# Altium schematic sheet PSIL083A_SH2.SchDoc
size 558 x 431 mm; Date: Not shown in title block; ApprovedBy: Not shown in title block; CheckedBy: Not shown in title block; Author: Not shown in title block; CompanyName: Not shown in title block; Engineer: Not shown in title block; Organization: Not shown in title block; Address1: Not shown in title block; Address2: Not shown in title block; Address3: Not shown in title block; Address4: Not shown in title block; DocumentNumber: 2; Revision: Use project parameter SCH_Rev; SheetNumber: 2; SheetTotal: 3; PageSetup: Record=PageOptions¦CenterHorizontal=True¦CenterVertical=True¦PrintScale=1.00¦XCorrection=1.00¦YCorrection=1.00¦PrintKind=0¦BorderSize=5000000¦LeftOffset=0¦BottomOffset=0¦Orientation=2¦PaperLength=1000¦PaperWidth=1000¦Scale=100¦PaperSource=15¦PrintQuality=600¦MediaType=1¦DitherType=10¦PaperKind=Letter¦PrintScaleMode=1
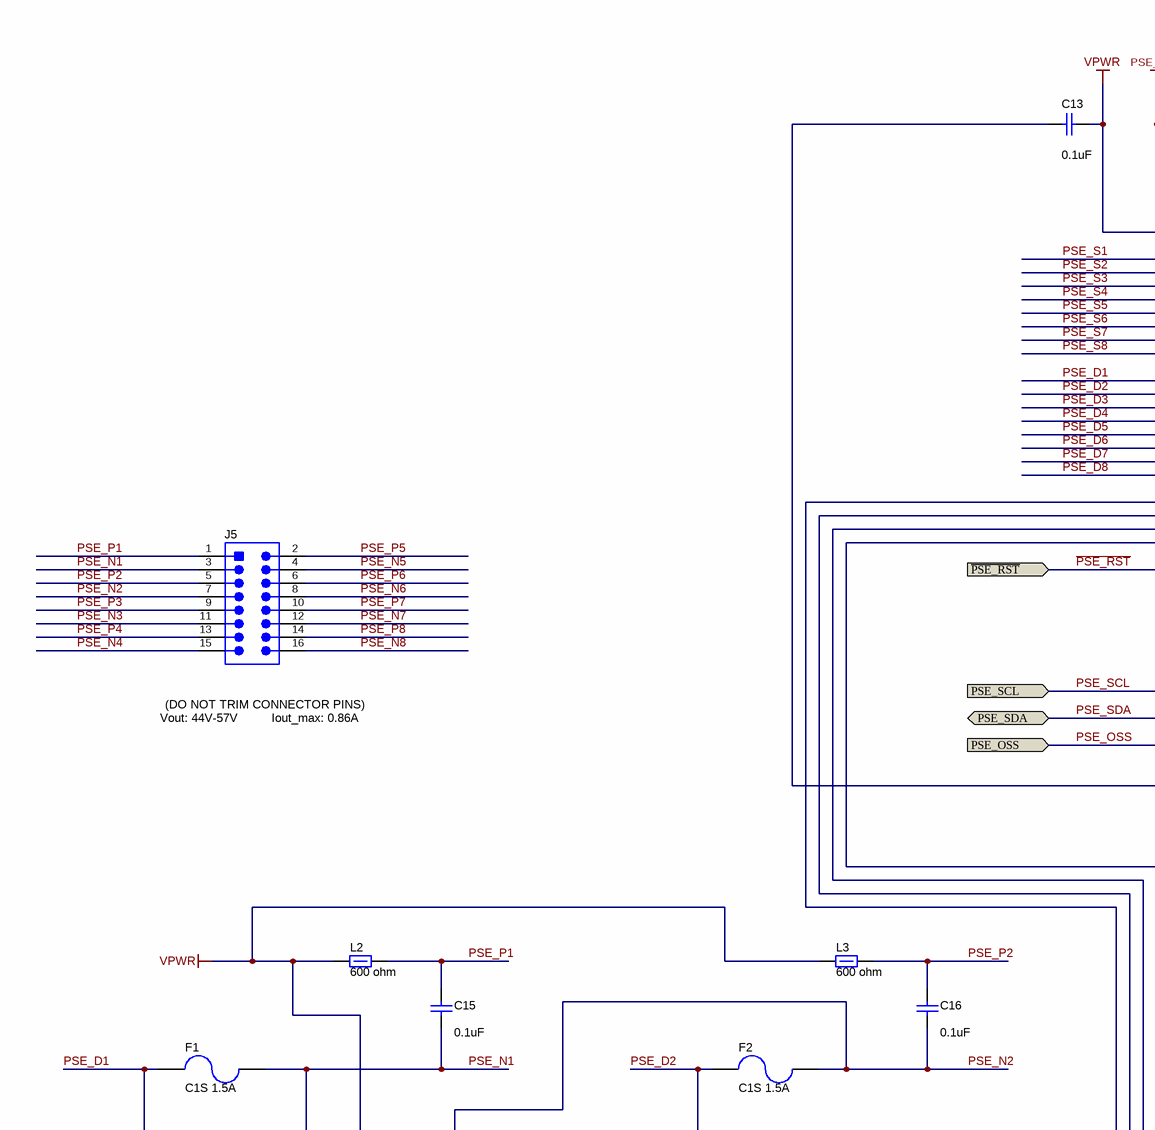
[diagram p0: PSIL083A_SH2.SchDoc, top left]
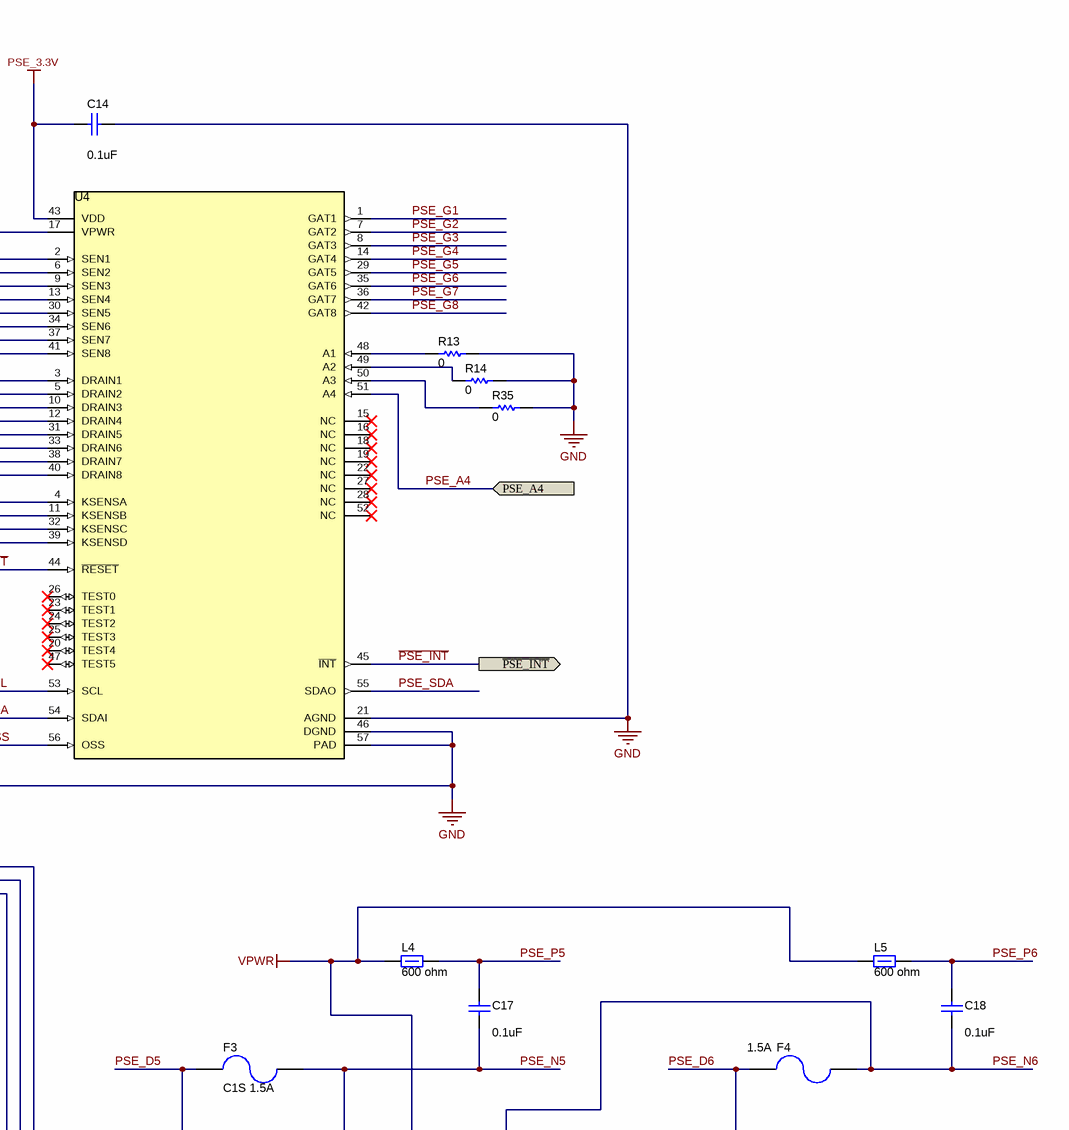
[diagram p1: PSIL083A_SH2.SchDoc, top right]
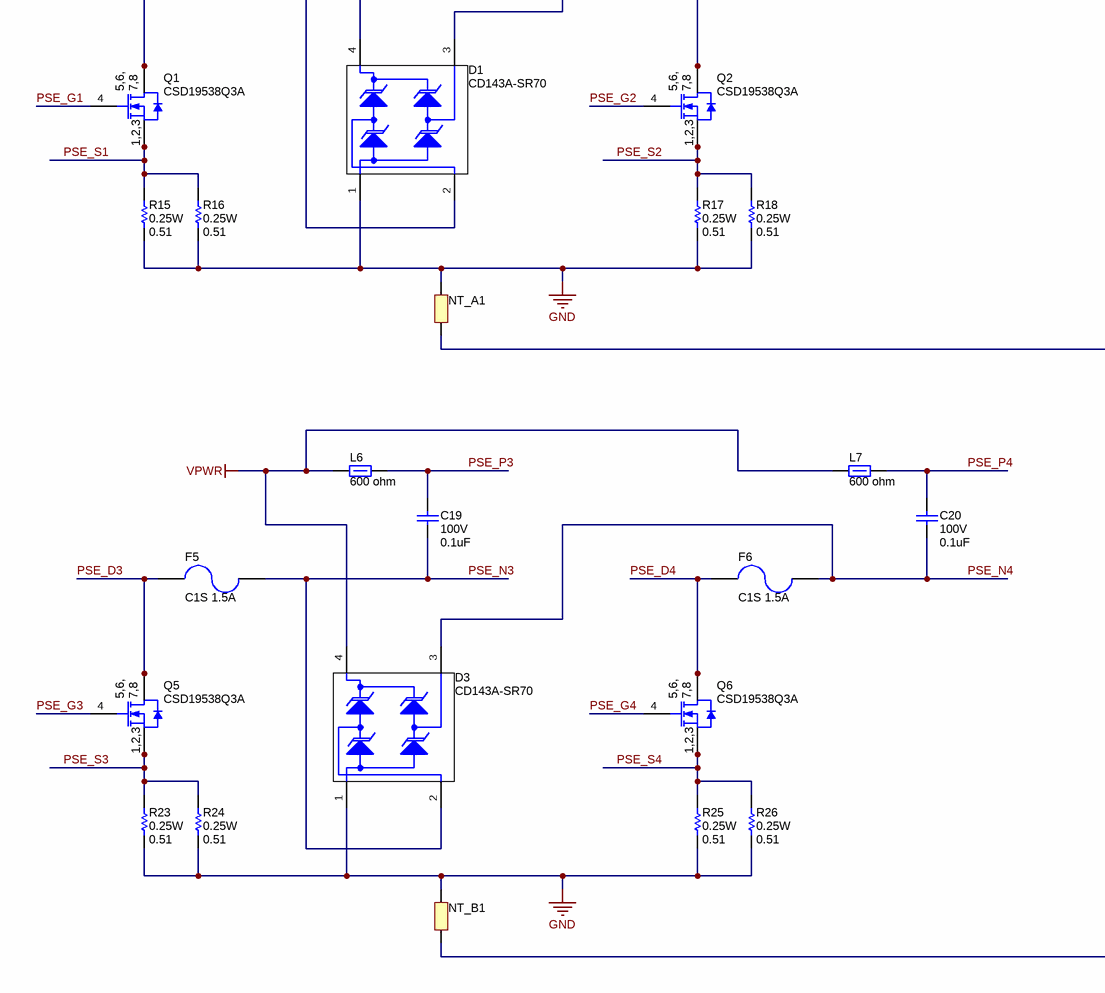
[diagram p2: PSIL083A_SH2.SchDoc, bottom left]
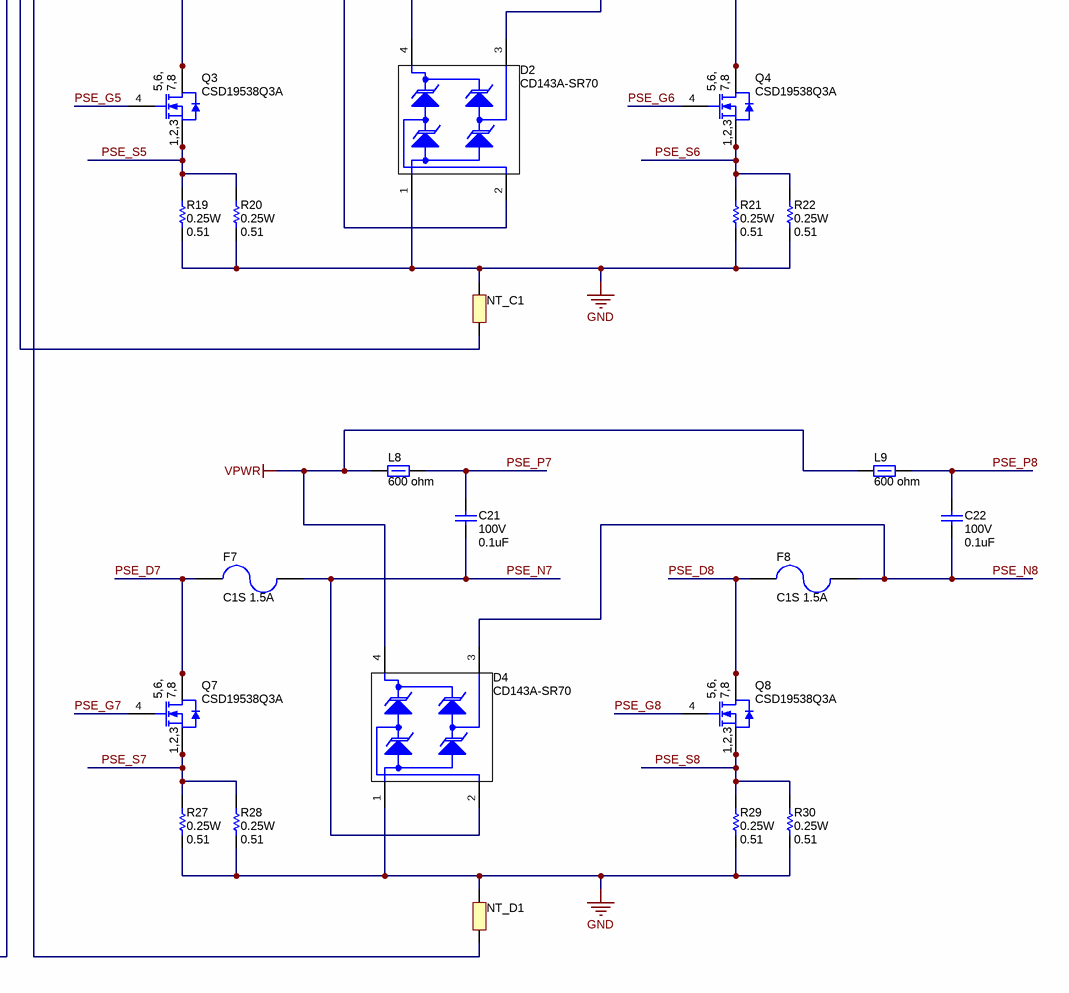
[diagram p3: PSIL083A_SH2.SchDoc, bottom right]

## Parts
C13  ValueDisplayed: 0.1uF  [0603]  (hidden comment: CGA3E3X7S2A104K080AB)
C14  ValueDisplayed: 0.1uF  [0805_HV]  (hidden comment: C0805C104K4RACTU)
C15  ValueDisplayed: 0.1uF  [0805_HV]  (hidden comment: C2012X7R2A104K125AA)
C16  ValueDisplayed: 0.1uF  [0805_HV]  (hidden comment: C2012X7R2A104K125AA)
C17  ValueDisplayed: 0.1uF  [0805_HV]  (hidden comment: C2012X7R2A104K125AA)
C18  ValueDisplayed: 0.1uF  [0805_HV]  (hidden comment: C2012X7R2A104K125AA)
C19  VDC_V: 100V  ValueDisplayed: 0.1uF  [0805_HV]  (hidden comment: C2012X7R2A104K125AA)
C20  VDC_V: 100V  ValueDisplayed: 0.1uF  [0805_HV]  (hidden comment: C2012X7R2A104K125AA)
C21  VDC_V: 100V  ValueDisplayed: 0.1uF  [0805_HV]  (hidden comment: C2012X7R2A104K125AA)
C22  VDC_V: 100V  ValueDisplayed: 0.1uF  [0805_HV]  (hidden comment: C2012X7R2A104K125AA)
D1  CD143A-SR70  [SOT-143-4]
D2  CD143A-SR70  [SOT-143-4]
D3  CD143A-SR70  [SOT-143-4]
D4  CD143A-SR70  [SOT-143-4]
F1  C1S 1.5A  [1206]
F2  C1S 1.5A  [1206]
F3  C1S 1.5A  [1206]
F4  Irating_A: 1.5A  [1206]  (hidden comment: C1S 1.5)
F5  C1S 1.5A  [1206]
F6  C1S 1.5A  [1206]
F7  C1S 1.5A  [1206]
F8  C1S 1.5A  [1206]
J5  TSW-108-09-G-D  [TSW-108-07-G-D]  (value not drawn)
L2  ValueDisplayed: 600 ohm  [0603]  (hidden comment: MPZ1608S601ATD25)
L3  ValueDisplayed: 600 ohm  [0603]  (hidden comment: MPZ1608S601ATD25)
L4  ValueDisplayed: 600 ohm  [0603]  (hidden comment: MPZ1608S601ATD25)
L5  ValueDisplayed: 600 ohm  [0603]  (hidden comment: MPZ1608S601ATD25)
L6  ValueDisplayed: 600 ohm  [0603]  (hidden comment: MPZ1608S601ATD25)
L7  ValueDisplayed: 600 ohm  [0603]  (hidden comment: MPZ1608S601ATD25)
L8  ValueDisplayed: 600 ohm  [0603]  (hidden comment: MPZ1608S601ATD25)
L9  ValueDisplayed: 600 ohm  [0603]  (hidden comment: MPZ1608S601ATD25)
NT_A1  Net-Tie  [Net-Tie_10milWide_30milLong]  (value not drawn)  (net tie, no BOM)
NT_B1  Net-Tie  [Net-Tie_10milWide_30milLong]  (value not drawn)  (net tie, no BOM)
NT_C1  Net-Tie  [Net-Tie_10milWide_30milLong]  (value not drawn)  (net tie, no BOM)
NT_D1  Net-Tie  [Net-Tie_10milWide_30milLong]  (value not drawn)  (net tie, no BOM)
Q1  CSD19538Q3A  [DNH0008A_NV]
Q2  CSD19538Q3A  [DNH0008A_NV]
Q3  CSD19538Q3A  [DNH0008A_NV]
Q4  CSD19538Q3A  [DNH0008A_NV]
Q5  CSD19538Q3A  [DNH0008A_NV]
Q6  CSD19538Q3A  [DNH0008A_NV]
Q7  CSD19538Q3A  [DNH0008A_NV]
Q8  CSD19538Q3A  [DNH0008A_NV]
R13  ValueDisplayed: 0  [0402]  (hidden comment: ERJ-2GE0R00X)
R14  ValueDisplayed: 0  [0402]  (hidden comment: ERJ-2GE0R00X)
R15  Value2: 0.25W  ValueDisplayed: 0.51  [0805L]  (hidden comment: CRM0805-FX-R510ELF)
R16  Value2: 0.25W  ValueDisplayed: 0.51  [0805L]  (hidden comment: CRM0805-FX-R510ELF)
R17  Value2: 0.25W  ValueDisplayed: 0.51  [0805L]  (hidden comment: CRM0805-FX-R510ELF)
R18  Value2: 0.25W  ValueDisplayed: 0.51  [0805L]  (hidden comment: CRM0805-FX-R510ELF)
R19  Value2: 0.25W  ValueDisplayed: 0.51  [0805L]  (hidden comment: CRM0805-FX-R510ELF)
R20  Value2: 0.25W  ValueDisplayed: 0.51  [0805L]  (hidden comment: CRM0805-FX-R510ELF)
R21  Value2: 0.25W  ValueDisplayed: 0.51  [0805L]  (hidden comment: CRM0805-FX-R510ELF)
R22  Value2: 0.25W  ValueDisplayed: 0.51  [0805L]  (hidden comment: CRM0805-FX-R510ELF)
R23  Value2: 0.25W  ValueDisplayed: 0.51  [0805L]  (hidden comment: CRM0805-FX-R510ELF)
R24  Value2: 0.25W  ValueDisplayed: 0.51  [0805L]  (hidden comment: CRM0805-FX-R510ELF)
R25  Value2: 0.25W  ValueDisplayed: 0.51  [0805L]  (hidden comment: CRM0805-FX-R510ELF)
R26  Value2: 0.25W  ValueDisplayed: 0.51  [0805L]  (hidden comment: CRM0805-FX-R510ELF)
R27  Value2: 0.25W  ValueDisplayed: 0.51  [0805L]  (hidden comment: CRM0805-FX-R510ELF)
R28  Value2: 0.25W  ValueDisplayed: 0.51  [0805L]  (hidden comment: CRM0805-FX-R510ELF)
R29  Value2: 0.25W  ValueDisplayed: 0.51  [0805L]  (hidden comment: CRM0805-FX-R510ELF)
R30  Value2: 0.25W  ValueDisplayed: 0.51  [0805L]  (hidden comment: CRM0805-FX-R510ELF)
R35  ValueDisplayed: 0  [0402]  (hidden comment: ERJ-2GE0R00X)
U4  TPS23880RTQR  [RTQ0056E]

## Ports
PSE_A4 (in), PSE_OSS (in), PSE_SCL (in), PSE_SDA (bidir), ~{PSE_INT} (out), ~{PSE_RST} (in)

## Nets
GND: C13.2 C14.2 D1.1(A) D2.1(A) D3.1(A) D4.1(A) NT_A1.2 NT_B1.2 NT_C1.2 NT_D1.2 R13.2 R14.2 R15.2 R16.2 R17.2 R18.2 R19.2 R20.2 R21.2 R22.2 R23.2 R24.2 R25.2 R26.2 R27.2 R28.2 R29.2 R30.2 R35.2 U4.21(AGND) U4.46(DGND) U4.57(PAD)
PSE_3.3V: C14.1 U4.43(VDD)
VPWR: C13.1 D1.4(K3) D2.4(K3) D3.4(K3) D4.4(K3) L2.1 L3.1 L4.1 L5.1 L6.1 L7.1 L8.1 L9.1 U4.17(VPWR)
~{PSE_INT}: U4.45(~{INT}) ; port ~{PSE_INT}
~{PSE_RST}: U4.44(~{RESET}) ; port ~{PSE_RST}
PSE_A4: U4.51(A4) ; port PSE_A4
PSE_D1: F1.2 Q1.5(D) Q1.6(D) Q1.7(D) Q1.8(D) Q1.9(D) U4.3(DRAIN1)
PSE_D2: F2.2 Q2.5(D) Q2.6(D) Q2.7(D) Q2.8(D) Q2.9(D) U4.5(DRAIN2)
PSE_D3: F5.2 Q5.5(D) Q5.6(D) Q5.7(D) Q5.8(D) Q5.9(D) U4.10(DRAIN3)
PSE_D4: F6.2 Q6.5(D) Q6.6(D) Q6.7(D) Q6.8(D) Q6.9(D) U4.12(DRAIN4)
PSE_D5: F3.2 Q3.5(D) Q3.6(D) Q3.7(D) Q3.8(D) Q3.9(D) U4.31(DRAIN5)
PSE_D6: F4.2 Q4.5(D) Q4.6(D) Q4.7(D) Q4.8(D) Q4.9(D) U4.33(DRAIN6)
PSE_D7: F7.2 Q7.5(D) Q7.6(D) Q7.7(D) Q7.8(D) Q7.9(D) U4.38(DRAIN7)
PSE_D8: F8.2 Q8.5(D) Q8.6(D) Q8.7(D) Q8.8(D) Q8.9(D) U4.40(DRAIN8)
PSE_G1: Q1.4(G) U4.1(GAT1)
PSE_G2: Q2.4(G) U4.7(GAT2)
PSE_G3: Q5.4(G) U4.8(GAT3)
PSE_G4: Q6.4(G) U4.14(GAT4)
PSE_G5: Q3.4(G) U4.29(GAT5)
PSE_G6: Q4.4(G) U4.35(GAT6)
PSE_G7: Q7.4(G) U4.36(GAT7)
PSE_G8: Q8.4(G) U4.42(GAT8)
PSE_N1: C15.2 D1.2(K1) F1.1 J5.3
PSE_N2: C16.2 D1.3(K2) F2.1 J5.7
PSE_N3: C19.2 D3.2(K1) F5.1 J5.11
PSE_N4: C20.2 D3.3(K2) F6.1 J5.15
PSE_N5: C17.2 D2.2(K1) F3.1 J5.4
PSE_N6: C18.2 D2.3(K2) F4.1 J5.8
PSE_N7: C21.2 D4.2(K1) F7.1 J5.12
PSE_N8: C22.2 D4.3(K2) F8.1 J5.16
PSE_OSS: U4.56(OSS) ; port PSE_OSS
PSE_P1: C15.1 J5.1 L2.2
PSE_P2: C16.1 J5.5 L3.2
PSE_P3: C19.1 J5.9 L6.2
PSE_P4: C20.1 J5.13 L7.2
PSE_P5: C17.1 J5.2 L4.2
PSE_P6: C18.1 J5.6 L5.2
PSE_P7: C21.1 J5.10 L8.2
PSE_P8: C22.1 J5.14 L9.2
PSE_S1: Q1.1(S) Q1.2(S) Q1.3(S) R15.1 R16.1 U4.2(SEN1)
PSE_S2: Q2.1(S) Q2.2(S) Q2.3(S) R17.1 R18.1 U4.6(SEN2)
PSE_S3: Q5.1(S) Q5.2(S) Q5.3(S) R23.1 R24.1 U4.9(SEN3)
PSE_S4: Q6.1(S) Q6.2(S) Q6.3(S) R25.1 R26.1 U4.13(SEN4)
PSE_S5: Q3.1(S) Q3.2(S) Q3.3(S) R19.1 R20.1 U4.30(SEN5)
PSE_S6: Q4.1(S) Q4.2(S) Q4.3(S) R21.1 R22.1 U4.34(SEN6)
PSE_S7: Q7.1(S) Q7.2(S) Q7.3(S) R27.1 R28.1 U4.37(SEN7)
PSE_S8: Q8.1(S) Q8.2(S) Q8.3(S) R29.1 R30.1 U4.41(SEN8)
PSE_SCL: U4.53(SCL) ; port PSE_SCL
PSE_SDA: U4.54(SDAI) U4.55(SDAO) ; port PSE_SDA
NetNT_A1_1: NT_A1.1 U4.4(KSENSA)
NetNT_B1_1: NT_B1.1 U4.11(KSENSB)
NetNT_C1_1: NT_C1.1 U4.32(KSENSC)
NetNT_D1_1: NT_D1.1 U4.39(KSENSD)
NetR13_1: R13.1 U4.48(A1)
NetR14_1: R14.1 U4.49(A2)
NetR35_1: R35.1 U4.50(A3)

Not connected (* = marked no-connect by the designer): U4 15(NC)* 16(NC)* 18(NC)* 19(NC)* 20(TEST4)* 22(NC)* 23(TEST1)* 24(TEST2)* 25(TEST3)* 26(TEST0)* 27(NC)* 28(NC)* 47(TEST5)* 52(NC)*

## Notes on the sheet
- Vout: 44V-57V
- (near J5) (DO NOT TRIM CONNECTOR PINS)
- Iout_max: 0.86A

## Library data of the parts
C13 = CMP-0007099-4: CAP, CERM, 0.1 uF, 100 V, +/- 10%, X7S, AEC-Q200 Grade 1, 0603; Manufacturer: TDK; TaMin_C: -55°C; ESR_ohm: 0.04959; Polarized: N; SizeAreaWB_mm2: 4.68; Value1: 0.04959 ohm; U/M: EA; Value: 0.1uF; TaMax_C: 125°C; SizeZ_mm: 1; SizeX_mm: 1.6; SizeY_mm: 0.8; Value2: 100V; SizeArea_mm2: 1.28; CompType: Capacitor; AEC Qualified: Y; Cap_F: 100nF; IRMS_A: 7.51618dA; AEC Category: Q200
C14 = CMP-0007724-2: CAP, CERM, 0.1 uF, 16 V, +/- 10%, X7R, 0805; Manufacturer: Kemet; TaMin_C: -55°C; ESR_ohm: 0.064; Polarized: N; SizeAreaWB_mm2: 6.75; Value1: 0.064 ohm; U/M: EA; Value: 0.1uF; TaMax_C: 125°C; SizeZ_mm: 1.45; SizeX_mm: 2; SizeY_mm: 1.25; Cap_Case: 0805; SizeArea_mm2: 2.5; CompType: Capacitor; Cap_F: 100nF; VDC_V: 16V; IRMS_A: 1.64A; AEC Category: Q200
C15-C18 = CMP-0007886-2: CAP, CERM, 0.1 uF, 100 V, +/- 10%, X7R, 0805; Manufacturer: TDK; TaMin_C: -55°C; ESR_ohm: 0.020726; Polarized: N; SizeAreaWB_mm2: 6.75; Value1: 0.020726 ohm; U/M: EA; Value: 0.1uF; TaMax_C: 125°C; SizeZ_mm: 1.45; SizeX_mm: 2; SizeY_mm: 1.25; Cap_Case: 0805; Value2: 100V; SizeArea_mm2: 2.5; CompType: Capacitor; Cap_F: 100nF; IRMS_A: 1.456A; AEC Category: Q200
C19-C22 = CMP-0007886-2: CAP, CERM, 0.1 uF, 100 V, +/- 10%, X7R, 0805; Manufacturer: TDK; TaMin_C: -55°C; ESR_ohm: 0.020726; Polarized: N; SizeAreaWB_mm2: 6.75; Value1: 0.020726 ohm; U/M: EA; Value: 0.1uF; TaMax_C: 125°C; SizeZ_mm: 1.45; SizeX_mm: 2; SizeY_mm: 1.25; Cap_Case: 0805; SizeArea_mm2: 2.5; Cap_F: 100nF; IRMS_A: 1.456A; AEC Category: Q200
D1-D4 = CMP-0002018-2: ESD Suppressor Diode Arrays, 7V, SMD; Manufacturer: Bourns; CompType: ESD Diode Array
F1-F3 F5-F8 = CMP-0003587-2: Fuse, 1.5 A, 63VAC/VDC, SMD; Manufacturer: Bel Fuse; PartNumber: C1S 1.5; SizeAreaWB_mm2: 10.92; VAC_V: 63V; SizeZ_mm: 1.35; SizeX_mm: 3.2; SizeY_mm: 1.6; SizeArea_mm2: 5.12; Rtyp_Ohm: 0.182; MeltingTyp: 0.27
F4 = CMP-0003587-2: Fuse, 1.5 A, 63VAC/VDC, SMD; Manufacturer: Bel Fuse; SizeAreaWB_mm2: 10.92; VAC_V: 63V; SizeZ_mm: 1.35; SizeX_mm: 3.2; SizeY_mm: 1.6; SizeArea_mm2: 5.12; Rtyp_Ohm: 0.182; MeltingTyp: 0.27
J5 = CMP-0075418-1: Header, 100mil, 8x2, Gold, TH; Manufacturer: Samtec; Pitch_mm: 2.54; Cert_VDE: N; Gender: Male; Cert_CSA: Y; Voltage_V: 550V; Green_REACh: Passed; Current_A: 6.3A; CT: False; Green_Lifecycle: Active; Row_Count: 2; CNHeader: True
L2-L9 = CMP-0078795-1: Ferrite Bead, 600 ohm @ 100 MHz, 1 A, 0603; Manufacturer: TDK; ZTyp@100MHz_Ohm: 600; SizeAreaWB_mm2: 4.68; DCR_ohm: 1.5d; Value1: 0.15 ohm; Value: 600 ohm; Imax_A: 1A; SizeZ_mm: 1; SizeX_mm: 1.6; SizeY_mm: 0.8; SizeArea_mm2: 1.28
NT_A1 NT_B1 NT_C1 NT_D1 = CMP-0078142-2: Single point connection between nets.
Q1 = CMP-0000969-3: MOSFET, N-CH, 100 V, 5 A, DNH0008A (VSONP-8); Alternate Manufacturer: None; Manufacturer: Texas Instruments; SizeZ_mm: 0.9; ChType: N; VdsMax_V: 100V; SizeX_mm: 3.3; SizeAreaWB_mm2: 18.49; Vgs_V: 20V; Value: 100V; SizeArea_mm2: 10.89; AEC Category: Q101; IdsMax_A: 5A; Value2: 7.2 nC; QgTyp_nC: 7.2; ChMode: Enhancement
Q2-Q8 = CMP-0000969-3: MOSFET, N-CH, 100 V, 5 A, DNH0008A (VSONP-8); Alternate Manufacturer: None; Manufacturer: Texas Instruments; SizeZ_mm: 0.9; ChType: N; Value2: 7.2 nC; VdsMax_V: 100V; SizeX_mm: 3.3; SizeAreaWB_mm2: 18.49; Vgs_V: 20V; QgTyp_nC: 7.2; Value: 100V; SizeArea_mm2: 10.89; AEC Category: Q101; IdsMax_A: 5A; ChMode: Enhancement
R13 R14 R35 = CMP-0026992-3: RES, 0, 5%, 0.1 W, AEC-Q200 Grade 0, 0402; Manufacturer: Panasonic; Power_W: 100mW; TempCo: 600 ppm/C; Value_Code: 0000; Value: 0; EIA_Code: E24; SizeX_mm: 1; SizeY_mm: 0.5; SizeZ_mm: 0.6; Value2: 0.1W; AEC Qualified: Y; VDC_V: 50V; AEC Category: Q200; SizeAreaWB_mm2: 3
R15-R30 = CMP-0021516-2: RES, 0.51, 1%, 0.25 W, 0805; Manufacturer: Bourns; Power_W: 250mW; TempCo: 100 ppm/C; Value_Code: R510; U/M: EA; Value: 0.51; EIA_Code: E96; Res_ohm: 5.1d; SizeX_mm: 2; SizeY_mm: 1.25; SizeZ_mm: 1.45; SizeArea_mm2: 2.5; CompType: Resistor; VDC_V: 0V; AEC Category: Q200
U4 = CMP-0074661-5: High-Power 8-Channel Power-over-Ethernet PSE with Programmable SRAM, RTQ0056E (VQFN-56); Manufacturer: Texas Instruments; Alternate PartNumber: TPS23880RTQT; SizeX_mm: 8.0; CompType: IC; SizeZ_mm: 1.0; SizeArea_mm2: 64.0; SizeAreaWB_mm2: 100.0; AEC Category: Q200; AEC Qualified: N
